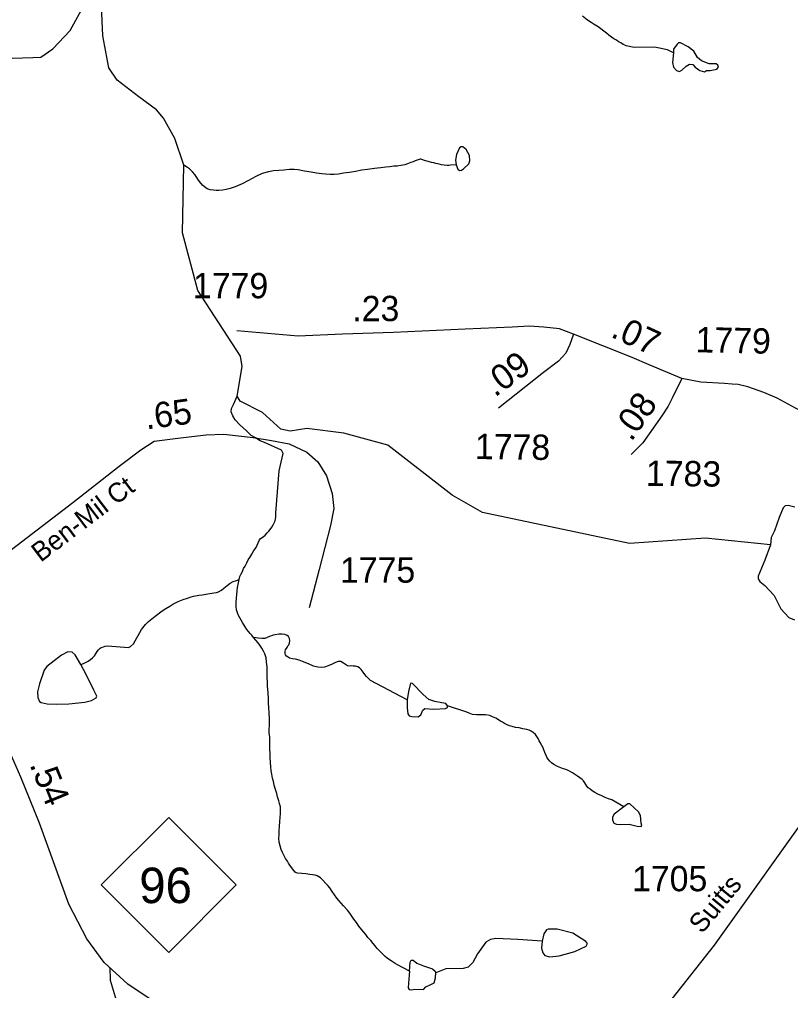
# Model space of a CAD drawing. Extents: x 2056842 to 2160602, y 826753 to 1016856.
# Drawn here: x 2129652 to 2133459, y 858350 to 863143 of the extents above; entities that cross this region are included whole.
import ezdxf

# ---------------------------------------------------------------- set-up
doc = ezdxf.new("R2010")
doc.units = 0
for name, color, linetype in [('Exist Hydrographic Creek Single Shore', 7, 'Continuous'), ('Exist Hydrographic Misc Water Feature', 7, 'Continuous'), ('Exist Road Non-System Type 51', 7, 'Continuous'), ('Exist Road Primary NC Attributed', 7, 'Continuous'), ('Exist Road Primary NC Service Mileage Hundredths English Label', 7, 'Continuous'), ('Exist Road Primary NC Shield CELL', 7, 'Continuous'), ('Exist Road Primary NC Shield Number Label', 7, 'Continuous'), ('Exist Road Secondary Mileage Hundredths English Label', 7, 'Continuous'), ('Exist Road Secondary Type 51 Attributed', 7, 'Continuous'), ('Exist Road Secondary Type 51 Label', 7, 'Continuous'), ('Exist Road Secondary Type 51 Number Label', 7, 'Continuous')]:
    doc.layers.add(name, color=color, linetype=linetype)

msp = doc.modelspace()

# ---------------------------------------------------------------- linework, layer by layer
at = {"layer": 'Exist Hydrographic Creek Single Shore'}
msp.add_lwpolyline([(2133359.6, 860549.4), (2133038.7, 860582.2), (2132663.7, 860557.1), (2131938.6, 860709.8), (2131788.7, 860795), (2131470.7, 861041), (2131253.7, 861101.3), (2131070.9, 861124.6), (2130988.3, 861111.2), (2130943.2, 861119.8), (2130853.2, 861202.4), (2130741.4, 861258.4), (2130726.8, 861282.7), (2130751.8, 861429.9), (2130743.9, 861480.9), (2130533.6, 861805.1), (2130457.7, 862088.9), (2130463.5, 862423.8), (2130419, 862554.8), (2130363.1, 862655.7), (2130329, 862695.9), (2130241.5, 862761.5), (2130135.8, 862843), (2130093.2, 862903.8), (2130064.1, 863061.9), (2130051.5, 863360.1)], dxfattribs=at)
at = {"layer": 'Exist Hydrographic Misc Water Feature'}
for points in [[(2129421.5, 862863.7), (2129478.6, 862906.3), (2129501.7, 862926.9), (2129515.1, 862935.4), (2129552.7, 862948.8), (2129615.9, 862952.5), (2129719.3, 862954.9), (2129758.2, 862957.3), (2129816.7, 862998.2), (2129903.3, 863088.7), (2130051.5, 863360.1)], [(2132880.6, 862978.1), (2132851.7, 862993.2), (2132795.1, 863004.8), (2132785.9, 863005.8), (2132687.2, 863004.5), (2132648.1, 863012.6), (2132640.9, 863015.3), (2132632.9, 863019.5), (2132620.8, 863027.2), (2132612.8, 863031.5), (2132606.9, 863035.7), (2132596.6, 863041.7), (2132586.6, 863046.8), (2132574.7, 863055.2), (2132562.6, 863065.3), (2132550.5, 863074.6), (2132536.7, 863085.5), (2132522.4, 863096.5), (2132509.5, 863106.7), (2132489.4, 863118.5), (2132474.2, 863127.9), (2132456.2, 863139.7), (2132432, 863158.2)], [(2132880.6, 862978.1), (2132876.8, 862930.4), (2132880.6, 862907.7), (2132895.6, 862891.4), (2132910.7, 862886.4), (2132923.3, 862892.7), (2132944.6, 862912.8), (2132960.9, 862921.6), (2132977.3, 862920.3), (2132988.6, 862906.5), (2133011.2, 862890.2), (2133033.8, 862883.9), (2133043.8, 862890.2), (2133062.6, 862891.4), (2133095.3, 862897.7), (2133104.1, 862907.7), (2133100.3, 862917.8), (2133091.5, 862924.1), (2133057.6, 862924.1), (2133019.9, 862937.9), (2132999.9, 862954.2), (2132981, 862986.9), (2132953.4, 863008.3), (2132915.7, 863027.1), (2132906.9, 863027.1), (2132899.4, 863020.8), (2132881.8, 862996.9), (2132880.6, 862978.1)], [(2131808.4, 862425.9), (2131817, 862404), (2131824.2, 862397.9), (2131835.2, 862399.1), (2131844.9, 862405.2), (2131870.4, 862430.7), (2131876.5, 862445.3), (2131874.1, 862472.1), (2131857.1, 862501.3), (2131841.3, 862513.4), (2131834, 862514.7), (2131825.5, 862509.8), (2131809.7, 862477), (2131806, 862447.8), (2131808.4, 862425.9)], [(2131808.4, 862425.9), (2131781.3, 862423.6), (2131772.7, 862422.2), (2131762.3, 862421.6), (2131748.7, 862423.5), (2131736.6, 862425.4), (2131724.7, 862428.1), (2131708.3, 862431.7), (2131697.9, 862434.4), (2131686.4, 862437.1), (2131670.6, 862441.6), (2131656.7, 862445.1), (2131634.5, 862452.9), (2131630.8, 862453.1), (2131625.1, 862451.4), (2131616.5, 862448.4), (2131606.4, 862444.4), (2131596.4, 862440.6), (2131584.7, 862436.8), (2131568.7, 862430.5), (2131554.8, 862425.9), (2131545.1, 862423.6), (2131534.7, 862422.2), (2131517.2, 862419.3), (2131500.6, 862418), (2131480.9, 862415.9), (2131460.8, 862413.1), (2131436.8, 862411.1), (2131420.9, 862409), (2131404.9, 862406.8), (2131370.8, 862402.6), (2131343.1, 862398.3), (2131311.1, 862392.4), (2131281.2, 862388.1), (2131253.1, 862383.8), (2131227.1, 862379.3), (2131207, 862377.3), (2131186.7, 862376.9), (2131163.1, 862379), (2131145.3, 862381), (2131119.8, 862384.9), (2131092.4, 862388.7), (2131059.1, 862394.3), (2131029.2, 862399.8), (2131009.1, 862401.9), (2130985.1, 862401.6), (2130957.2, 862398.8), (2130933.4, 862396.9), (2130907.2, 862394.9), (2130881.4, 862390.6), (2130850, 862382.2), (2130819.6, 862368.1), (2130784, 862347.5), (2130752.2, 862331.7), (2130717.9, 862316.8), (2130693.1, 862308.3), (2130673.4, 862303), (2130654.4, 862300.1), (2130636.1, 862298), (2130624.4, 862298.2), (2130610.1, 862300.2), (2130594.1, 862302.2), (2130580.1, 862307.4), (2130572.1, 862311.7), (2130558, 862323.5), (2130547.9, 862335.2), (2130542, 862343.5), (2130534, 862355.1), (2130527.6, 862363.5), (2130518.6, 862376.8), (2130507.3, 862390.9), (2130491.4, 862405.2), (2130481.5, 862412.8), (2130463.5, 862423.8)], [(2130737, 860379.2), (2130741.1, 860392.9), (2130746.8, 860406.8), (2130753, 860418.9), (2130758.9, 860432.8), (2130766.7, 860444.9), (2130774.7, 860461.2), (2130782.5, 860474.9), (2130790.5, 860487), (2130800.2, 860503.3), (2130810, 860521.2), (2130821.9, 860537.3), (2130831.7, 860560), (2130837.5, 860573.9), (2130841.4, 860579.6), (2130847.5, 860583.5), (2130855.5, 860590), (2130865.2, 860598), (2130875.2, 860608.4), (2130883, 860616.4), (2130891, 860626), (2130899, 860636.6), (2130904.7, 860648), (2130914.6, 860668.3), (2130918.5, 860688.7), (2130918.5, 860708.4), (2130934.5, 860914.8), (2130954.1, 861000.6), (2130946.8, 861017.6), (2130863.1, 861054), (2130849.2, 861060), (2130841.2, 861063.4), (2130817.2, 861078), (2130796.9, 861089.8), (2130772.7, 861111.6), (2130740.5, 861142.7), (2130718.1, 861166.9), (2130706.2, 861186.8), (2130697.8, 861206.7), (2130700.1, 861223.1), (2130709.8, 861242.6), (2130726.8, 861282.7)], [(2133481.1, 860735.5), (2133447.1, 860744), (2133432.5, 860742.8), (2133422.8, 860731.8), (2133403.3, 860684.4), (2133380.2, 860618.7), (2133363.2, 860585.9), (2133359.6, 860549.4)], [(2133359.6, 860549.4), (2133331.6, 860474), (2133300, 860394.9), (2133300, 860381.6), (2133307.3, 860368.2), (2133332.8, 860348.7), (2133379, 860300.1), (2133410.6, 860234.4), (2133450.7, 860191.8), (2133478.7, 860179.7)], [(2129955.2, 859959.3), (2129969.5, 859964.3), (2129981.2, 859969.8), (2129991.2, 859976.2), (2130003.1, 859984.2), (2130013, 859992.2), (2130023, 860002.6), (2130031, 860014.7), (2130036.8, 860022.8), (2130042.7, 860030.9), (2130050.7, 860038.9), (2130056.4, 860042.9), (2130066.7, 860046.8), (2130076.5, 860049.1), (2130088.4, 860051.3), (2130190.6, 860043.5), (2130200.3, 860048.3), (2130216.1, 860061.7), (2130255.7, 860132.3), (2130275.4, 860156.6), (2130289.4, 860170.9), (2130323.2, 860197.4), (2130356.6, 860223.7), (2130374.7, 860235.6), (2130394.4, 860247.5), (2130410.4, 860256.2), (2130436.4, 860270.5), (2130460.2, 860280.6), (2130482.1, 860286.8), (2130500, 860292.9), (2130511.9, 860296.8), (2130537.9, 860301.1), (2130553.9, 860303.3), (2130582, 860307.7), (2130611.9, 860312), (2130625.9, 860314.2), (2130635.9, 860318.1), (2130649.9, 860326), (2130661.7, 860336.4), (2130677.3, 860348.4), (2130693.3, 860360.3), (2130707.3, 860368.2), (2130723.5, 860374.4), (2130737, 860379.2)], [(2130807.7, 860093), (2130799.7, 860103.1), (2130791.8, 860111.5), (2130775.3, 860131.5), (2130767.1, 860144.8), (2130753.4, 860167.1), (2130740.9, 860188.8), (2130734.7, 860201.2), (2130729.2, 860213.6), (2130724.7, 860228.5), (2130722.4, 860244.9), (2130722.4, 860265.4), (2130724.5, 860285.9), (2130725.9, 860304.7), (2130727.8, 860322.7), (2130729.6, 860339.1), (2130733.5, 860362.8), (2130737, 860379.2)], [(2131566.7, 859784.4), (2131385.4, 859880.1), (2131375.1, 859890.2), (2131365.1, 859900.3), (2131356.9, 859910.3), (2131349.1, 859921.9), (2131338.8, 859933.6), (2131330.8, 859941.9), (2131322.6, 859947.9), (2131311.4, 859951.4), (2131300.7, 859951.6), (2131292.7, 859951.7), (2131280.6, 859951.2), (2131272.6, 859953), (2131266.7, 859955.6), (2131252.7, 859964.9), (2131238.8, 859973.4), (2131225.2, 859973.7), (2131212.7, 859969), (2131196.7, 859960.3), (2131176.8, 859952.5), (2131159, 859946.3), (2131144.9, 859944.2), (2131125, 859946.2), (2131104.9, 859951.6), (2131078.8, 859961.9), (2131050.7, 859973.2), (2131032.7, 859981), (2131014.6, 859985.4), (2131000.7, 859987.3), (2130986.3, 859990.9), (2130978.8, 859995.2), (2130970.4, 860001), (2130966.5, 860006.9), (2130964.4, 860012.7), (2130964.4, 860018.4), (2130964.2, 860025), (2130966.3, 860030.7), (2130974.2, 860042.8), (2130978.1, 860051), (2130981.8, 860056.6), (2130985.9, 860064.7), (2130988, 860077), (2130985.7, 860086.9), (2130981.4, 860096.8), (2130973.6, 860102.8), (2130963.4, 860107.1), (2130949.4, 860108.9), (2130933.6, 860108.5), (2130915.4, 860106.3), (2130905.8, 860104.1), (2130887.7, 860097.9), (2130875.6, 860091.6), (2130863.9, 860087.8), (2130849.6, 860088.1), (2130831.7, 860089.2), (2130807.7, 860093)], [(2130849.4, 860040.5), (2130839.7, 860053.8), (2130830.5, 860066.3), (2130819.8, 860079.6), (2130807.7, 860093)], [(2129955.2, 859959.3), (2129928.1, 860007), (2129912.3, 860020.4), (2129891.6, 860021.6), (2129860, 860004.6), (2129788.3, 859949.8), (2129774.9, 859931.6), (2129751.8, 859863.5), (2129740.9, 859823.4), (2129743.3, 859796.6), (2129751.8, 859777.1), (2129760.3, 859771.1), (2129789.5, 859765), (2129834.5, 859762.5), (2129896.5, 859765), (2129975.5, 859773.5), (2130008.3, 859780.8), (2130031.4, 859794.2), (2130035, 859802.7), (2130020.4, 859833.1), (2129981.5, 859909.7), (2129955.2, 859959.3)], [(2131578.5, 858445.5), (2131519.7, 858477.3), (2131507.6, 858483.3), (2131497.7, 858489.2), (2131487.5, 858496.8), (2131469.4, 858508.6), (2131457.4, 858518.7), (2131449.4, 858526.3), (2131443.4, 858532.9), (2131433.2, 858542.2), (2131425.2, 858550.6), (2131419.2, 858558), (2131409, 858570.6), (2131398.9, 858582.2), (2131386.6, 858596.5), (2131372.7, 858612.4), (2131362.4, 858625.7), (2131352.4, 858638.2), (2131342.1, 858649.9), (2131328, 858667.4), (2131315.9, 858685.7), (2131304, 858701.5), (2131293.9, 858717.3), (2131283.7, 858731.5), (2131271.4, 858747.3), (2131253.1, 858767.4), (2131228.9, 858794.9), (2131218.9, 858806.6), (2131196.7, 858838.2), (2131184.4, 858856.6), (2131174.4, 858868.2), (2131164.1, 858879.9), (2131150.2, 858894.2), (2131138.1, 858905.9), (2131130.1, 858911.8), (2131121.9, 858916.1), (2131111.8, 858919.6), (2131086.2, 858923.3), (2131065.9, 858925.4), (2131046, 858927.5), (2131025.9, 858928.7), (2131019.2, 858930.5), (2131013.8, 858934.7), (2130999.9, 858950.6), (2130987.6, 858968.9), (2130981.6, 858978.9), (2130975.5, 858988.8), (2130966.7, 859002.1), (2130959.1, 859014.6), (2130950.9, 859031.2), (2130945.1, 859046.1), (2130939, 859064.2), (2130934.7, 859082.4), (2130933.6, 859102), (2130934.3, 859118.4), (2130934.9, 859139.7), (2130935.9, 859160.2), (2130937.7, 859184), (2130939.4, 859204.5), (2130941.4, 859224.1), (2130941.9, 859241.3), (2130940.6, 859256.9), (2130936.9, 859272.6), (2130932.8, 859286.6), (2130926.7, 859306.4), (2130922.4, 859322.1), (2130916.6, 859341.9), (2130910.3, 859364.2), (2130906.2, 859382.3), (2130901.9, 859398), (2130897.8, 859417.7), (2130895.5, 859434.2), (2130893.5, 859453.9), (2130891.6, 859475.3), (2130891, 859500), (2130889.8, 859522.1), (2130888.7, 859540.2), (2130888.3, 859558.2), (2130888.1, 859572.2), (2130888.1, 859586.1), (2130887.9, 859601.7), (2130885.9, 859619.8), (2130885.7, 859636.2), (2130887.7, 859659.9), (2130887.1, 859691.9), (2130884.8, 859719.9), (2130883, 859746.2), (2130882.6, 859768.3), (2130881.4, 859792.1), (2130880.1, 859820), (2130877.9, 859853.7), (2130876.4, 859874.2), (2130875.4, 859895.6), (2130875.2, 859921.8), (2130875, 859948.1), (2130873, 859970.3), (2130870.7, 859991.7), (2130864.3, 860011.5), (2130858.2, 860025.6), (2130849.4, 860040.5)], [(2131766, 859755.2), (2131757.5, 859766.2), (2131738.1, 859769.8), (2131704, 859775.9), (2131673.7, 859785.7), (2131645.7, 859811.2), (2131592.2, 859865.9), (2131584.9, 859867.1), (2131581.3, 859859.8), (2131574, 859825.8), (2131566.7, 859784.4)], [(2131566.7, 859784.4), (2131566.7, 859745.5), (2131569.1, 859716.3), (2131576.4, 859705.4), (2131589.8, 859701.7), (2131621.4, 859700.5), (2131634.8, 859710.2), (2131643.3, 859733.4), (2131654.2, 859741.9), (2131698, 859739.4), (2131755.1, 859741.9), (2131766, 859746.7), (2131766, 859755.2)], [(2132636.3, 859256.6), (2132576.9, 859290.4), (2132560.1, 859296.4), (2132543.9, 859303.4), (2132527.9, 859310.3), (2132507.8, 859319.7), (2132493.7, 859327.4), (2132479.7, 859335.9), (2132469.7, 859343.4), (2132460.5, 859351), (2132453.5, 859359.4), (2132443.4, 859375.1), (2132437.5, 859384.4), (2132431.1, 859391), (2132406.9, 859408.7), (2132383, 859424.9), (2132364.9, 859435), (2132354.9, 859438.5), (2132332.7, 859446.3), (2132308.7, 859455.9), (2132290.7, 859466.1), (2132278.4, 859473.7), (2132270.4, 859482.1), (2132262.4, 859492.1), (2132256.4, 859502.1), (2132252.1, 859509.5), (2132246.2, 859525.3), (2132241.9, 859537.6), (2132238, 859547.6), (2132231.8, 859559.2), (2132223.8, 859573.3), (2132218.7, 859582.4), (2132213.4, 859593.1), (2132207.4, 859603.1), (2132199.4, 859613.1), (2132189.4, 859623.2), (2132179.1, 859630.8), (2132169.1, 859635.1), (2132157, 859638.7), (2132146.9, 859640.5), (2132136.9, 859642.3), (2132119.3, 859645.9), (2132101.2, 859648.8), (2132085, 859652.5), (2132071.1, 859656), (2132060.4, 859661.1), (2132046.7, 859667.1), (2132036.8, 859673.9), (2132027, 859679.9), (2132004.8, 859693.5), (2131988.6, 859701.2), (2131974.5, 859707.2), (2131952.8, 859711), (2131930.4, 859710.6), (2131908.7, 859711), (2131889.2, 859712.3), (2131872.6, 859718.3), (2131860.5, 859724.3), (2131766, 859755.2)], [(2132636.3, 859256.6), (2132588.9, 859220.1), (2132580.4, 859205.6), (2132580.4, 859192.2), (2132586.4, 859176.4), (2132599.8, 859170.3), (2132618, 859169.1), (2132661.8, 859170.3), (2132701.9, 859161.8), (2132722.6, 859159.3), (2132725, 859164.2), (2132722.6, 859176.4), (2132718.9, 859214.1), (2132708, 859232.3), (2132666.6, 859271.2), (2132655.7, 859271.2), (2132636.3, 859256.6)], [(2132232.7, 858593.8), (2132230.3, 858558.6), (2132236.4, 858536.7), (2132246.1, 858523.3), (2132271.6, 858516), (2132317.8, 858520.9), (2132394.4, 858542.8), (2132450.3, 858569.5), (2132456.4, 858581.7), (2132449.1, 858591.4), (2132384.7, 858632.7), (2132306.9, 858652.2), (2132263.1, 858653.4), (2132254.6, 858649.8), (2132241.3, 858630.3), (2132232.7, 858593.8)], [(2132232.7, 858593.8), (2132112.4, 858602.3), (2132004.2, 858606), (2131977.5, 858602.3), (2131955.6, 858589), (2131914.3, 858531.8), (2131890, 858488), (2131868.1, 858464.9), (2131842.6, 858458.8), (2131757.5, 858456.4), (2131708.5, 858436.9)], [(2131578.5, 858445.5), (2131580.9, 858490.5), (2131587, 858499), (2131596.7, 858499), (2131613.7, 858485.6), (2131647.8, 858472.2), (2131691.5, 858456.4), (2131704.9, 858445.5), (2131708.5, 858436.9)], [(2131578.5, 858445.5), (2131572.4, 858385.9), (2131571.2, 858362.8), (2131577.3, 858354.3), (2131588.2, 858353), (2131604, 858356.7), (2131646.5, 858354.3), (2131658.7, 858367.6), (2131680.6, 858377.4), (2131700, 858388.3), (2131707.3, 858412.6), (2131708.5, 858436.9)]]:
    msp.add_lwpolyline(points, dxfattribs=at)
at = {"layer": 'Exist Road Non-System Type 51'}
msp.add_lwpolyline([(2130099.5, 858462.8), (2130100.6, 858400.5), (2130150.5, 858236.3), (2130138, 858186.4)], dxfattribs=at)
at = {"layer": 'Exist Road Primary NC Attributed'}
msp.add_lwpolyline([(2130497.1, 858207.1), (2130442, 858229.9), (2130322.2, 858290.8), (2130187.3, 858382), (2130071.4, 858488.5), (2129985.9, 858604.5), (2129895.6, 858776.6), (2129751.2, 859175.9), (2129659.1, 859403.2), (2129602, 859534.4), (2129470.9, 859665.6), (2129313.2, 859817.7), (2129163.2, 859911.8), (2128965.6, 860010), (2128745.3, 860062.7), (2128610, 860084.3)], dxfattribs=at)
at = {"layer": 'Exist Road Primary NC Shield CELL'}
msp.add_lwpolyline([(2130056.7, 858871.1), (2130389.7, 859204.1), (2130722.7, 858871.1), (2130389.7, 858538.1)], close=True, dxfattribs=at)
at = {"layer": 'Exist Road Secondary Type 51 Attributed'}
for points in [[(2132388.1, 861588.8), (2132319.3, 861615), (2132242.1, 861624.6), (2132169.1, 861628.8), (2132085.1, 861623.3), (2131853.3, 861614.7), (2131499.8, 861598.5), (2131247.8, 861588.8), (2131028.9, 861580), (2130726.5, 861605.3)], [(2132388.1, 861588.8), (2132370.2, 861537.8), (2132349.6, 861495.1), (2132313.8, 861456.5), (2132239.4, 861400), (2132017, 861223.6)], [(2132921.8, 861371.1), (2132762, 861438.6), (2132678, 861474.1), (2132388.1, 861588.8)], [(2132921.8, 861371.1), (2132875, 861273.3), (2132854.3, 861234.7), (2132824, 861186.4), (2132730.4, 861052.8), (2132672.5, 860994.9)], [(2134102.8, 861080.3), (2133950.6, 861075.1), (2133881.9, 861081), (2133825.7, 861087.5), (2133713.9, 861120.7), (2133598.1, 861167.1), (2133483.7, 861225), (2133392.8, 861273.3), (2133328.1, 861302.2), (2133248.2, 861329.7), (2133201.4, 861340.8), (2133171.1, 861343.5), (2133133.9, 861346.3), (2133016.8, 861351.8), (2132921.8, 861371.1)], [(2129591.5, 860510.4), (2129916, 860759.2), (2130145, 860937.9), (2130252.2, 861019.2), (2130317.4, 861061.1), (2130448, 861078.3), (2130574.8, 861093.1), (2130662.3, 861095.6), (2130806.3, 861079.6), (2130896.2, 861064.8), (2130983.7, 861048.8), (2131071.1, 861006.9), (2131125.3, 860958.8), (2131168.4, 860891.1), (2131196.7, 860802.4), (2131204.1, 860728.4), (2131188.7, 860645.9), (2131132, 860428.8), (2131083.6, 860239.3)], [(2134102.8, 861080.3), (2134162.6, 860667.7), (2134177.9, 860471.8), (2134154.1, 860286.4), (2134100.9, 860111.5), (2133998.3, 859898.5), (2133586.9, 859281.5), (2133082.4, 858573.2), (2132805.7, 858223.3), (2132747, 858066.4), (2132729.9, 857954.2), (2132719.6, 857812), (2132718.8, 857784.3)]]:
    msp.add_lwpolyline(points, dxfattribs=at)

# ---------------------------------------------------------------- texts
at = {"layer": 'Exist Road Primary NC Service Mileage Hundredths English Label'}
msp.add_text('.54', height=125, rotation=292.0767, dxfattribs=at).set_placement((2129701.2, 859465.5))
at = {"layer": 'Exist Road Primary NC Shield Number Label'}
msp.add_text('96', height=175, dxfattribs=at).set_placement((2130243.9, 858781.4))
at = {"layer": 'Exist Road Secondary Mileage Hundredths English Label'}
for s, rotation, p in [('.23', 0.1098, (2131295.8, 861653.4)), ('.07', 335.1535, (2132566.3, 861578.3)), ('.09', 36.216, (2131999.9, 861275.7)), ('.08', 54.9827, (2132673.2, 861055.1)), ('.65', 7.527, (2130279.2, 861119.1))]:
    msp.add_text(s, height=125, rotation=rotation, dxfattribs=at).set_placement(p)
at = {"layer": 'Exist Road Secondary Type 51 Label'}
for s, rotation, p in [('Ben-Mil Ct', 37.176, (2129757.3, 860460.9)), ('Suitts', 50.431, (2133022.2, 858626.2))]:
    msp.add_text(s, height=95, rotation=rotation, dxfattribs=at).set_placement(p)
at = {"layer": 'Exist Road Secondary Type 51 Number Label'}
for s, rotation, p in [('1779', 359.9154, (2130508.9, 861767)), ('1779', 358.8357, (2132989, 861500.2)), ('1778', 359.2481, (2131900, 860973.3)), ('1783', 359.356, (2132744.5, 860841))]:
    msp.add_text(s, height=125, rotation=rotation, dxfattribs=at).set_placement(p)
for s, p in [('1775', (2131234.7, 860362.8)), ('1705', (2132676.6, 858840))]:
    msp.add_text(s, height=125, dxfattribs=at).set_placement(p)

doc.saveas('drawing.dxf')
